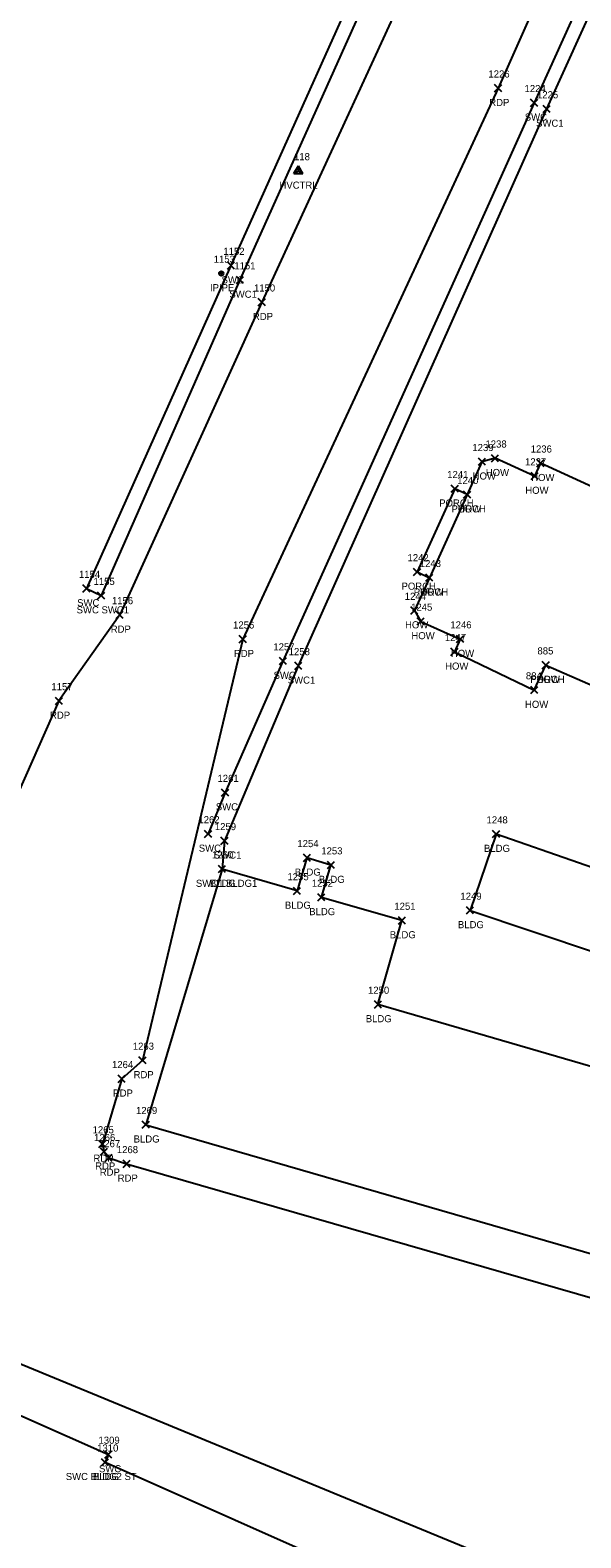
# Model space of a CAD drawing. Extents: x 1767353 to 1772625, y 740790 to 747702.
# Drawn here: x 1769882.6 to 1770037.2, y 741990.7 to 742414.3 of the extents above; entities that cross this region are included whole.
import ezdxf

# ---------------------------------------------------------------- set-up
doc = ezdxf.new("R2010")
doc.units = 0
for name, color, linetype in [('C_A', 7, 'Continuous'), ('C_I', 7, 'Continuous'), ('CPSM', 7, 'Continuous'), ('L_A', 7, 'Continuous'), ('L_I', 7, 'Continuous'), ('L_TIC', 7, 'Continuous'), ('LBC', 7, 'Continuous'), ('LBF', 7, 'Continuous'), ('M_A', 7, 'Continuous'), ('M_I', 7, 'Continuous'), ('MPIP', 7, 'Continuous'), ('P_A', 7, 'Continuous'), ('P_I', 7, 'Continuous'), ('P_TIC', 7, 'Continuous'), ('PET', 7, 'Continuous'), ('R_A', 7, 'Continuous'), ('R_I', 7, 'Continuous'), ('R_TIC', 7, 'Continuous'), ('RSW', 7, 'Continuous')]:
    doc.layers.add(name, color=color, linetype=linetype)

msp = doc.modelspace()

# ---------------------------------------------------------------- linework, layer by layer
at = {"layer": 'CPSM'}
for p, q in [((1769956.66, 742374.07), (1769957.91, 742376.23)), ((1769956.66, 742374.07), (1769957.91, 742376.23)), ((1769956.66, 742374.07), (1769957.91, 742376.23)), ((1769956.66, 742374.07), (1769957.91, 742376.23)), ((1769956.66, 742374.07), (1769957.91, 742376.23)), ((1769956.66, 742374.07), (1769957.91, 742376.23)), ((1769956.66, 742374.07), (1769957.91, 742376.23)), ((1769956.66, 742374.07), (1769957.91, 742376.23)), ((1769956.66, 742374.07), (1769957.91, 742374.79)), ((1769956.66, 742374.07), (1769957.91, 742374.79)), ((1769956.66, 742374.07), (1769957.91, 742374.79)), ((1769956.66, 742374.07), (1769957.91, 742374.79)), ((1769956.66, 742374.07), (1769957.91, 742374.79)), ((1769956.66, 742374.07), (1769957.91, 742374.79)), ((1769956.66, 742374.07), (1769957.91, 742374.79)), ((1769956.66, 742374.07), (1769957.91, 742374.79)), ((1769959.16, 742374.07), (1769957.91, 742376.23)), ((1769957.91, 742374.79), (1769957.91, 742376.23)), ((1769959.16, 742374.07), (1769957.91, 742376.23)), ((1769957.91, 742374.79), (1769957.91, 742376.23)), ((1769959.16, 742374.07), (1769957.91, 742376.23)), ((1769957.91, 742374.79), (1769957.91, 742376.23)), ((1769959.16, 742374.07), (1769957.91, 742376.23)), ((1769957.91, 742374.79), (1769957.91, 742376.23)), ((1769959.16, 742374.07), (1769957.91, 742376.23)), ((1769957.91, 742374.79), (1769957.91, 742376.23)), ((1769959.16, 742374.07), (1769957.91, 742376.23)), ((1769957.91, 742374.79), (1769957.91, 742376.23)), ((1769959.16, 742374.07), (1769957.91, 742376.23)), ((1769957.91, 742374.79), (1769957.91, 742376.23)), ((1769959.16, 742374.07), (1769957.91, 742376.23)), ((1769957.91, 742374.79), (1769957.91, 742376.23)), ((1769957.91, 742374.79), (1769957.91, 742374.79)), ((1769957.91, 742374.79), (1769959.16, 742374.07)), ((1769957.91, 742374.79), (1769957.91, 742374.79)), ((1769957.91, 742374.79), (1769959.16, 742374.07)), ((1769957.91, 742374.79), (1769957.91, 742374.79)), ((1769957.91, 742374.79), (1769959.16, 742374.07)), ((1769957.91, 742374.79), (1769957.91, 742374.79)), ((1769957.91, 742374.79), (1769959.16, 742374.07)), ((1769957.91, 742374.79), (1769957.91, 742374.79)), ((1769957.91, 742374.79), (1769959.16, 742374.07)), ((1769957.91, 742374.79), (1769957.91, 742374.79)), ((1769957.91, 742374.79), (1769959.16, 742374.07)), ((1769957.91, 742374.79), (1769957.91, 742374.79)), ((1769957.91, 742374.79), (1769959.16, 742374.07)), ((1769957.91, 742374.79), (1769957.91, 742374.79)), ((1769957.91, 742374.79), (1769959.16, 742374.07)), ((1769956.66, 742374.07), (1769959.16, 742374.07)), ((1769956.66, 742374.07), (1769959.16, 742374.07)), ((1769956.66, 742374.07), (1769959.16, 742374.07)), ((1769956.66, 742374.07), (1769959.16, 742374.07)), ((1769956.66, 742374.07), (1769959.16, 742374.07)), ((1769956.66, 742374.07), (1769959.16, 742374.07)), ((1769956.66, 742374.07), (1769959.16, 742374.07)), ((1769956.66, 742374.07), (1769959.16, 742374.07))]:
    msp.add_line(p, q, dxfattribs=at)
at = {"layer": 'L_TIC'}
for points in [[(1770012.14, 742293.05), (1770014.14, 742295.05)], [(1770014.14, 742293.05), (1770012.14, 742295.05)], [(1770008.46, 742292.06), (1770010.46, 742294.06)], [(1770010.46, 742292.06), (1770008.46, 742294.06)], [(1770023.24, 742288.05), (1770025.24, 742290.05)], [(1770025.24, 742288.05), (1770023.24, 742290.05)], [(1770024.89, 742291.65), (1770026.89, 742293.65)], [(1770026.89, 742291.65), (1770024.89, 742293.65)], [(1770000.83, 742284.48), (1770002.83, 742286.48)], [(1770002.83, 742284.48), (1770000.83, 742286.48)], [(1770004.29, 742282.82), (1770006.29, 742284.82)], [(1770006.29, 742282.82), (1770004.29, 742284.82)], [(1770004.29, 742282.82), (1770006.29, 742284.82)], [(1770006.29, 742282.82), (1770004.29, 742284.82)], [(1769990.25, 742261.1), (1769992.25, 742263.1)], [(1769992.25, 742261.1), (1769990.25, 742263.1)], [(1769993.69, 742259.48), (1769995.69, 742261.48)], [(1769995.69, 742259.48), (1769993.69, 742261.48)], [(1769993.69, 742259.48), (1769995.69, 742261.48)], [(1769995.69, 742259.48), (1769993.69, 742261.48)], [(1769989.47, 742250.25), (1769991.47, 742252.25)], [(1769991.47, 742250.25), (1769989.47, 742252.25)], [(1769991.25, 742247.2), (1769993.25, 742249.2)], [(1769993.25, 742247.2), (1769991.25, 742249.2)], [(1770002.33, 742242.23), (1770004.33, 742244.23)], [(1770004.33, 742242.23), (1770002.33, 742244.23)], [(1770000.73, 742238.65), (1770002.73, 742240.65)], [(1770002.73, 742238.65), (1770000.73, 742240.65)], [(1770026.4, 742234.92), (1770028.4, 742236.92)], [(1770028.4, 742234.92), (1770026.4, 742236.92)], [(1770026.4, 742234.92), (1770028.4, 742236.92)], [(1770028.4, 742234.92), (1770026.4, 742236.92)], [(1770023.15, 742227.91), (1770025.15, 742229.91)], [(1770025.15, 742227.91), (1770023.15, 742229.91)], [(1770012.44, 742187.44), (1770014.44, 742189.44)], [(1770014.44, 742187.44), (1770012.44, 742189.44)], [(1769959.32, 742180.77), (1769961.32, 742182.77)], [(1769961.32, 742180.77), (1769959.32, 742182.77)], [(1769966.04, 742178.73), (1769968.04, 742180.73)], [(1769968.04, 742178.73), (1769966.04, 742180.73)], [(1769935.48, 742177.62), (1769937.48, 742179.62)], [(1769937.48, 742177.62), (1769935.48, 742179.62)], [(1769956.53, 742171.47), (1769958.53, 742173.47)], [(1769958.53, 742171.47), (1769956.53, 742173.47)], [(1769963.36, 742169.66), (1769965.36, 742171.66)], [(1769965.36, 742169.66), (1769963.36, 742171.66)], [(1770005.11, 742166), (1770007.11, 742168)], [(1770007.11, 742166), (1770005.11, 742168)], [(1769985.99, 742163.16), (1769987.99, 742165.16)], [(1769987.99, 742163.16), (1769985.99, 742165.16)], [(1769979.24, 742139.57), (1769981.24, 742141.57)], [(1769981.24, 742139.57), (1769979.24, 742141.57)], [(1769914.07, 742105.78), (1769916.07, 742107.78)], [(1769916.07, 742105.78), (1769914.07, 742107.78)], [(1769902.62, 742010.94), (1769904.62, 742012.94)], [(1769904.62, 742010.94), (1769902.62, 742012.94)]]:
    msp.add_lwpolyline(points, dxfattribs=at)
at = {"layer": 'LBC'}
for points in [[(1770025.89, 742292.65), (1770024.24, 742289.05), (1770013.14, 742294.05), (1770009.46, 742293.06), (1770005.29, 742283.82), (1769994.69, 742260.48), (1769990.47, 742251.25), (1769992.25, 742248.2), (1770003.33, 742243.23), (1770001.73, 742239.65)], [(1770048.35, 742282.37), (1770025.89, 742292.65)], [(1770001.73, 742239.65), (1770024.15, 742228.91)], [(1770024.15, 742228.91), (1770027.4, 742235.92)], [(1770013.44, 742188.44), (1770006.11, 742167), (1770095.25, 742137.08), (1770093.19, 742131.45), (1770117.61, 742122.52)], [(1770082.76, 742164.28), (1770013.44, 742188.44)], [(1769980.24, 742140.57), (1769986.99, 742164.16), (1769964.36, 742170.66), (1769967.04, 742179.73), (1769960.32, 742181.77), (1769957.53, 742172.47), (1769936.48, 742178.62), (1769915.07, 742106.78), (1770081.26, 742058.61), (1770081.97, 742060.63), (1770086.55, 742059.45), (1770093.85, 742084.71), (1770088.83, 742086.05), (1770095.35, 742107.06)], [(1770095.35, 742107.06), (1769980.24, 742140.57)], [(1769903.62, 742011.94), (1770013.7, 741962.95), (1770004.7, 741896.15)]]:
    msp.add_lwpolyline(points, dxfattribs=at)
at = {"layer": 'LBF'}
for points in [[(1770005.29, 742283.82), (1770001.83, 742285.48), (1769991.25, 742262.1), (1769994.69, 742260.48)], [(1770027.4, 742235.92), (1770046.47, 742227.59), (1770048.51, 742232.55)]]:
    msp.add_lwpolyline(points, dxfattribs=at)
at = {"layer": 'MPIP'}
for radius in [0.625, 0.0833]:
    msp.add_circle((1769936.25, 742345.97), radius, dxfattribs=at)
at = {"layer": 'P_TIC'}
for points in [[(1770013.02, 742397.02), (1770015.02, 742399.02)], [(1770015.02, 742397.02), (1770013.02, 742399.02)], [(1769946.65, 742336.89), (1769948.65, 742338.89)], [(1769948.65, 742336.89), (1769946.65, 742338.89)], [(1769906.74, 742249.04), (1769908.74, 742251.04)], [(1769908.74, 742249.04), (1769906.74, 742251.04)], [(1769941.32, 742242.2), (1769943.32, 742244.2)], [(1769943.32, 742242.2), (1769941.32, 742244.2)], [(1769889.69, 742224.86), (1769891.69, 742226.86)], [(1769891.69, 742224.86), (1769889.69, 742226.86)], [(1769913.15, 742123.85), (1769915.15, 742125.85)], [(1769915.15, 742123.85), (1769913.15, 742125.85)], [(1769907.32, 742118.68), (1769909.32, 742120.68)], [(1769909.32, 742118.68), (1769907.32, 742120.68)], [(1769901.88, 742100.36), (1769903.88, 742102.36)], [(1769903.88, 742100.36), (1769901.88, 742102.36)], [(1769902.35, 742098.19), (1769904.35, 742100.19)], [(1769904.35, 742098.19), (1769902.35, 742100.19)], [(1769903.66, 742096.46), (1769905.66, 742098.46)], [(1769905.66, 742096.46), (1769903.66, 742098.46)], [(1769908.68, 742094.79), (1769910.68, 742096.79)], [(1769910.68, 742094.79), (1769908.68, 742096.79)]]:
    msp.add_lwpolyline(points, dxfattribs=at)
at = {"layer": 'PET'}
for points in [[(1770147.48, 742699.94), (1770126.77, 742647.43), (1770093.35, 742575.6), (1770087.72, 742564.06), (1770014.02, 742398.02), (1769942.32, 742243.2), (1769914.15, 742124.85), (1769908.32, 742119.68), (1769902.88, 742101.36), (1769903.35, 742099.19), (1769904.66, 742097.46), (1769909.68, 742095.79), (1770083.39, 742045.68), (1770106.4, 742043.42), (1770086.96, 742009.25), (1770086.23, 742007.27), (1770086.55, 742005.47), (1770087.9, 742003.62), (1770089.26, 742002.56), (1770097.29, 741998.16), (1770140.08, 741981.73)], [(1770020.73, 742570.11), (1770043.61, 742558.57), (1769998.45, 742448.54), (1769947.65, 742337.89), (1769907.74, 742250.04), (1769890.69, 742225.86), (1769843.08, 742118.46), (1769841.73, 742116.98), (1769840.43, 742116.75), (1769837.14, 742117.6), (1769825.35, 742123.03), (1769532.9, 742252.54)], [(1769720.25, 742093.61), (1769723.36, 742100.56), (1769724.18, 742101.86), (1769726.31, 742102.72), (1769729.14, 742101.78), (1770016.5, 741983.21), (1770029.17, 741977.28), (1770032.55, 741973.71), (1770033.81, 741969.69), (1770033.78, 741964.69), (1770032.81, 741956.25), (1770024.83, 741957.14), (1770016.33, 741894.01)]]:
    msp.add_lwpolyline(points, dxfattribs=at)
at = {"layer": 'R_TIC'}
for points in [[(1770023.1, 742392.92), (1770025.1, 742394.92)], [(1770025.1, 742392.92), (1770023.1, 742394.92)], [(1770026.61, 742391.19), (1770028.61, 742393.19)], [(1770028.61, 742391.19), (1770026.61, 742393.19)], [(1769937.98, 742347.19), (1769939.98, 742349.19)], [(1769939.98, 742347.19), (1769937.98, 742349.19)], [(1769940.49, 742343.14), (1769942.49, 742345.14)], [(1769942.49, 742343.14), (1769940.49, 742345.14)], [(1769897.43, 742256.44), (1769899.43, 742258.44)], [(1769899.43, 742256.44), (1769897.43, 742258.44)], [(1769901.52, 742254.45), (1769903.52, 742256.45)], [(1769903.52, 742254.45), (1769901.52, 742256.45)], [(1769901.52, 742254.45), (1769903.52, 742256.45)], [(1769903.52, 742254.45), (1769901.52, 742256.45)], [(1769952.58, 742236.06), (1769954.58, 742238.06)], [(1769954.58, 742236.06), (1769952.58, 742238.06)], [(1769956.88, 742234.71), (1769958.88, 742236.71)], [(1769958.88, 742234.71), (1769956.88, 742236.71)], [(1769936.36, 742199.11), (1769938.36, 742201.11)], [(1769938.36, 742199.11), (1769936.36, 742201.11)], [(1769931.58, 742187.49), (1769933.58, 742189.49)], [(1769933.58, 742187.49), (1769931.58, 742189.49)], [(1769936.16, 742185.55), (1769938.16, 742187.55)], [(1769938.16, 742185.55), (1769936.16, 742187.55)], [(1769935.48, 742177.62), (1769937.48, 742179.62)], [(1769937.48, 742177.62), (1769935.48, 742179.62)], [(1769903.56, 742013.13), (1769905.56, 742015.13)], [(1769905.56, 742013.13), (1769903.56, 742015.13)], [(1769902.62, 742010.94), (1769904.62, 742012.94)], [(1769904.62, 742010.94), (1769902.62, 742012.94)]]:
    msp.add_lwpolyline(points, dxfattribs=at)
at = {"layer": 'RSW'}
for points in [[(1770098.34, 742558.06), (1770024.1, 742393.92), (1769953.58, 742237.06), (1769937.36, 742200.11), (1769932.58, 742188.49)], [(1770098.34, 742558.06), (1770101.99, 742556.46), (1770027.61, 742392.19), (1769957.88, 742235.71), (1769937.16, 742186.55), (1769936.48, 742178.62)], [(1770031.85, 742546.17), (1770028.71, 742548.34), (1769986.57, 742454.53), (1769938.98, 742348.19), (1769898.43, 742257.44), (1769902.52, 742255.45)], [(1770031.85, 742546.17), (1769990.14, 742452.72), (1769941.49, 742344.14), (1769902.52, 742255.45)], [(1769725.34, 742093.64), (1769904.56, 742014.13), (1769903.62, 742011.94)]]:
    msp.add_lwpolyline(points, dxfattribs=at)

# ---------------------------------------------------------------- texts
at = {"layer": 'C_A'}
msp.add_text('HVCTRL', height=2, dxfattribs=at).set_placement((1769952.6, 742369.79))
msp.add_text('HVCTRL', height=2, dxfattribs=at).set_placement((1769952.6, 742369.79))
msp.add_text('HVCTRL', height=2, dxfattribs=at).set_placement((1769952.6, 742369.79))
msp.add_text('HVCTRL', height=2, dxfattribs=at).set_placement((1769952.6, 742369.79))
msp.add_text('HVCTRL', height=2, dxfattribs=at).set_placement((1769952.6, 742369.79))
msp.add_text('HVCTRL', height=2, dxfattribs=at).set_placement((1769952.6, 742369.79))
msp.add_text('HVCTRL', height=2, dxfattribs=at).set_placement((1769952.6, 742369.79))
msp.add_text('HVCTRL', height=2, dxfattribs=at).set_placement((1769952.6, 742369.79))
at = {"layer": 'C_I'}
msp.add_text('118', height=2, dxfattribs=at).set_placement((1769956.68, 742377.79))
msp.add_text('118', height=2, dxfattribs=at).set_placement((1769956.68, 742377.79))
msp.add_text('118', height=2, dxfattribs=at).set_placement((1769956.68, 742377.79))
msp.add_text('118', height=2, dxfattribs=at).set_placement((1769956.68, 742377.79))
msp.add_text('118', height=2, dxfattribs=at).set_placement((1769956.68, 742377.79))
msp.add_text('118', height=2, dxfattribs=at).set_placement((1769956.68, 742377.79))
msp.add_text('118', height=2, dxfattribs=at).set_placement((1769956.68, 742377.79))
msp.add_text('118', height=2, dxfattribs=at).set_placement((1769956.68, 742377.79))
at = {"layer": 'L_A'}
for s, p in [('HOW', (1770006.84, 742288.06)), ('HOW', (1770010.52, 742289.05)), ('HOW', (1770021.62, 742284.05)), ('HOW', (1770023.27, 742287.65)), ('PORCH', (1769997.45, 742280.48)), ('PORCH', (1770000.91, 742278.82)), ('HOW', (1770002.68, 742278.82)), ('PORCH', (1769986.87, 742257.1)), ('PORCH', (1769990.31, 742255.48)), ('HOW', (1769992.08, 742255.48)), ('HOW', (1769987.86, 742246.25)), ('HOW', (1769989.64, 742243.2)), ('HOW', (1770000.72, 742238.23)), ('HOW', (1769999.11, 742234.65)), ('PORCH', (1770023.02, 742230.92)), ('HOW', (1770024.78, 742230.92)), ('HOW', (1770021.54, 742223.91)), ('BLDG', (1770010.03, 742183.44)), ('BLDG', (1769933.07, 742173.62)), ('BLDG', (1769956.91, 742176.77)), ('BLDG', (1769963.63, 742174.73)), ('BLDG', (1769954.12, 742167.47)), ('BLDG', (1769960.95, 742165.66)), ('BLDG', (1770002.7, 742162)), ('BLDG', (1769983.58, 742159.16)), ('BLDG', (1769976.83, 742135.57)), ('BLDG', (1769911.66, 742101.78)), ('BLDG', (1769900.21, 742006.94))]:
    msp.add_text(s, height=2, dxfattribs=at).set_placement(p)
at = {"layer": 'L_I'}
for s, p in [('1238', (1770010.44, 742297.05)), ('1239', (1770006.76, 742296.06)), ('1236', (1770023.14, 742295.65)), ('1241', (1769999.7, 742288.48)), ('1237', (1770021.55, 742292.05)), ('1240', (1770002.51, 742286.82)), ('1240', (1770002.51, 742286.82)), ('1242', (1769988.56, 742265.1)), ('1243', (1769992, 742263.48)), ('1243', (1769992, 742263.48)), ('1244', (1769987.78, 742254.25)), ('1245', (1769989.56, 742251.2)), ('1246', (1770000.58, 742246.23)), ('1247', (1769999.03, 742242.65)), ('885', (1770025.04, 742238.92)), ('885', (1770025.04, 742238.92)), ('884', (1770021.79, 742231.91)), ('1248', (1770010.75, 742191.44)), ('1254', (1769957.63, 742184.77)), ('1253', (1769964.34, 742182.73)), ('1260', (1769933.66, 742181.62)), ('1255', (1769954.84, 742175.47)), ('1252', (1769961.67, 742173.66)), ('1249', (1770003.41, 742170)), ('1251', (1769984.86, 742167.16)), ('1250', (1769977.46, 742143.57)), ('1269', (1769912.32, 742109.78)), ('1310', (1769901.41, 742014.94))]:
    msp.add_text(s, height=2, dxfattribs=at).set_placement(p)
at = {"layer": 'M_A'}
msp.add_text('IPIPE', height=2, dxfattribs=at).set_placement((1769933.09, 742340.97))
at = {"layer": 'M_I'}
msp.add_text('1153', height=2, dxfattribs=at).set_placement((1769934.13, 742348.97))
at = {"layer": 'P_A'}
for p in [(1770011.5, 742393.02), (1769945.14, 742332.89), (1769905.22, 742245.04), (1769939.8, 742238.2), (1769888.18, 742220.86), (1769911.64, 742119.85), (1769905.81, 742114.68), (1769900.36, 742096.36), (1769900.84, 742094.19), (1769902.14, 742092.46), (1769907.17, 742090.79)]:
    msp.add_text('RDP', height=2, dxfattribs=at).set_placement(p)
at = {"layer": 'P_I'}
for s, p in [('1226', (1770011.27, 742401.02)), ('1150', (1769945.44, 742340.89)), ('1156', (1769905.56, 742253.04)), ('1256', (1769939.57, 742246.2)), ('1157', (1769888.56, 742228.86)), ('1263', (1769911.41, 742127.85)), ('1264', (1769905.58, 742122.68)), ('1265', (1769900.14, 742104.36)), ('1266', (1769900.55, 742102.19)), ('1267', (1769901.92, 742100.46)), ('1268', (1769906.94, 742098.79))]:
    msp.add_text(s, height=2, dxfattribs=at).set_placement(p)
at = {"layer": 'R_A'}
for s, p in [('SWC', (1770021.47, 742388.92)), ('SWC1', (1770024.65, 742387.19)), ('SWC', (1769936.35, 742343.19)), ('SWC1', (1769938.53, 742339.14)), ('SWC SWC1', (1769895.65, 742250.45)), ('SWC SWC1', (1769895.65, 742250.45)), ('SWC', (1769895.79, 742252.44)), ('SWC', (1769950.94, 742232.06)), ('SWC1', (1769954.92, 742230.71)), ('SWC', (1769934.72, 742195.11)), ('SWC', (1769929.94, 742183.49)), ('SWC1', (1769934.2, 742181.55)), ('SWC1 BLDG1', (1769929.13, 742173.62)), ('SWC', (1769901.92, 742009.13)), ('SWC BLDG2 ST', (1769892.59, 742006.94))]:
    msp.add_text(s, height=2, dxfattribs=at).set_placement(p)
at = {"layer": 'R_I'}
for s, p in [('1224', (1770021.41, 742396.92)), ('1225', (1770024.92, 742395.19)), ('1152', (1769936.86, 742351.19)), ('1151', (1769939.93, 742347.14)), ('1154', (1769896.3, 742260.44)), ('1155', (1769900.39, 742258.45)), ('1155', (1769900.39, 742258.45)), ('1257', (1769950.89, 742240.06)), ('1258', (1769955.19, 742238.71)), ('1261', (1769935.19, 742203.11)), ('1262', (1769929.84, 742191.49)), ('1259', (1769934.46, 742189.55)), ('1260', (1769933.66, 742181.62)), ('1309', (1769901.78, 742017.13)), ('1310', (1769901.41, 742014.94))]:
    msp.add_text(s, height=2, dxfattribs=at).set_placement(p)

doc.saveas('drawing.dxf')
